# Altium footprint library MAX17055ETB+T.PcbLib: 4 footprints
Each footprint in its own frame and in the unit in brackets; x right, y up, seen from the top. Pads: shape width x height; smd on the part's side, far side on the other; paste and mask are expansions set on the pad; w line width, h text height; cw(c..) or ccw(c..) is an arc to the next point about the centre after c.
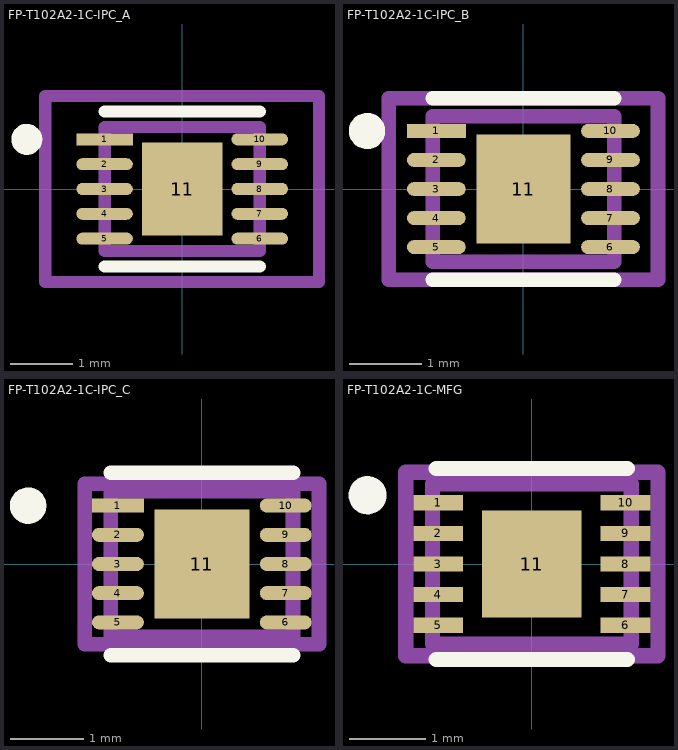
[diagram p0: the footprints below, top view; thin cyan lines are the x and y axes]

## FP-T102A2-1C-IPC_A [mm]
pads (11):
  rect 0.911x0.192 smd paste+0 mask+0: 1(-1.251,0.8)
  rrect100% 0.911x0.192 smd paste+0 mask+0: 2(-1.251,0.4) 3(-1.251,0) 4(-1.251,-0.4) 5(-1.251,-0.8) 6(1.251,-0.8) 7(1.251,-0.4) 8(1.251,0) 9(1.251,0.4) 10(1.251,0.8)
  rect 1.3x1.5 smd paste-1000 mask+0: 11(0,0)
Top Overlay:
  circle w0.25: c-2.506,0.8 r0.125
  lines w0.2: -1.25,-1.25 1.25,-1.25 ; -1.25,1.25 1.25,1.25
Top Paste:
  rectangle: -0.394,-0.494 0.394,0.494
Mechanical 5:
  lines w0.2: -2.206,-1.5 2.206,-1.5 2.206,1.5 -2.206,1.5 -2.206,-1.5
  text ".Designator" at 0,-0.001 h1
Mechanical 13:
  lines w0.2: -1.25,-1 1.25,-1 1.25,1 -1.25,1 -1.25,-1
Mechanical 15:
  lines w0.2: -2.206,-1.5 2.206,-1.5 2.206,1.5 -2.206,1.5 -2.206,-1.5
Mechanical 16:
  lines w0.1: -0.5,0 0.5,0 ; 0,-0.5 0,0.5
3D body "IC_Maxim_Integrated_MAX17055ETB+T_eec.STEP": height 0.25, standoff 0, extent -2.206,-1.5 2.206,1.5

## FP-T102A2-1C-IPC_B [mm]
pads (11):
  rect 0.811x0.192 smd paste+0 mask+0: 1(-1.201,0.8)
  rrect100% 0.811x0.192 smd paste+0 mask+0: 2(-1.201,0.4) 3(-1.201,0) 4(-1.201,-0.4) 5(-1.201,-0.8) 6(1.201,-0.8) 7(1.201,-0.4) 8(1.201,0) 9(1.201,0.4) 10(1.201,0.8)
  rect 1.3x1.5 smd paste-1000 mask+0: 11(0,0)
Top Overlay:
  circle w0.25: c-2.156,0.8 r0.125
  lines w0.2: -1.25,-1.25 1.25,-1.25 ; -1.25,1.25 1.25,1.25
Top Paste:
  rectangle: -0.394,-0.494 0.394,0.494
Mechanical 5:
  lines w0.2: -1.856,-1.25 1.856,-1.25 1.856,1.25 -1.856,1.25 -1.856,-1.25
  text ".Designator" at 0,-0.001 h1
Mechanical 13:
  lines w0.2: -1.25,-1 1.25,-1 1.25,1 -1.25,1 -1.25,-1
Mechanical 15:
  lines w0.2: -1.856,-1.25 1.856,-1.25 1.856,1.25 -1.856,1.25 -1.856,-1.25
Mechanical 16:
  lines w0.1: -0.5,0 0.5,0 ; 0,-0.5 0,0.5
3D body "IC_Maxim_Integrated_MAX17055ETB+T_eec.STEP": height 0.25, standoff 0, extent -1.856,-1.25 1.856,1.25

## FP-T102A2-1C-IPC_C [mm]
pads (11):
  rect 0.711x0.192 smd paste+0 mask+0: 1(-1.151,0.8)
  rrect100% 0.711x0.192 smd paste+0 mask+0: 2(-1.151,0.4) 3(-1.151,0) 4(-1.151,-0.4) 5(-1.151,-0.8) 6(1.151,-0.8) 7(1.151,-0.4) 8(1.151,0) 9(1.151,0.4) 10(1.151,0.8)
  rect 1.3x1.5 smd paste-1000 mask+0: 11(0,0)
Top Overlay:
  circle w0.25: c-2.381,0.8 r0.125
  lines w0.2: -1.25,-1.25 1.25,-1.25 ; -1.25,1.25 1.25,1.25
Top Paste:
  rectangle: -0.394,-0.494 0.394,0.494
Mechanical 5:
  lines w0.2: -1.606,-1.1 1.606,-1.1 1.606,1.1 -1.606,1.1 -1.606,-1.1
  text ".Designator" at 0,-0.001 h1
Mechanical 13:
  lines w0.2: -1.25,-1 1.25,-1 1.25,1 -1.25,1 -1.25,-1
Mechanical 15:
  lines w0.2: -1.606,-1.1 1.606,-1.1 1.606,1.1 -1.606,1.1 -1.606,-1.1
Mechanical 16:
  lines w0.1: -0.5,0 0.5,0 ; 0,-0.5 0,0.5
3D body "IC_Maxim_Integrated_MAX17055ETB+T_eec.STEP": height 0.25, standoff 0, extent -1.606,-1.1 1.606,1.1

## FP-T102A2-1C-MFG [mm]
pads (11):
  rect 0.65x0.2 smd paste+0 mask+0: 1(-1.225,0.8) 2(-1.225,0.4) 3(-1.225,0) 4(-1.225,-0.4) 5(-1.225,-0.8) 6(1.225,-0.8) 7(1.225,-0.4) 8(1.225,0) 9(1.225,0.4) 10(1.225,0.8)
  rect 1.3x1.4 smd paste+0 mask+0: 11(0,0)
Top Overlay:
  circle w0.25: c-2.15,0.9 r0.125
  lines w0.2: -1.25,-1.25 1.25,-1.25 ; -1.25,1.25 1.25,1.25
Mechanical 5:
  lines w0.2: -1.65,-1.2 1.65,-1.2 1.65,1.2 -1.65,1.2 -1.65,-1.2
  text ".Designator" at 0,0.188 h1
Mechanical 13:
  lines w0.2: -1.3,-1.05 1.3,-1.05 1.3,1.05 -1.3,1.05 -1.3,-1.05
Mechanical 15:
  lines w0.2: -1.65,-1.2 1.65,-1.2 1.65,1.2 -1.65,1.2 -1.65,-1.2
Mechanical 16:
  lines w0.1: -0.5,0 0.5,0 ; 0,-0.5 0,0.5
3D body "IC_Maxim_Integrated_MAX17055ETB+T_eec.STEP": height 0.25, standoff 0, extent -1.65,-1.2 1.65,1.2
